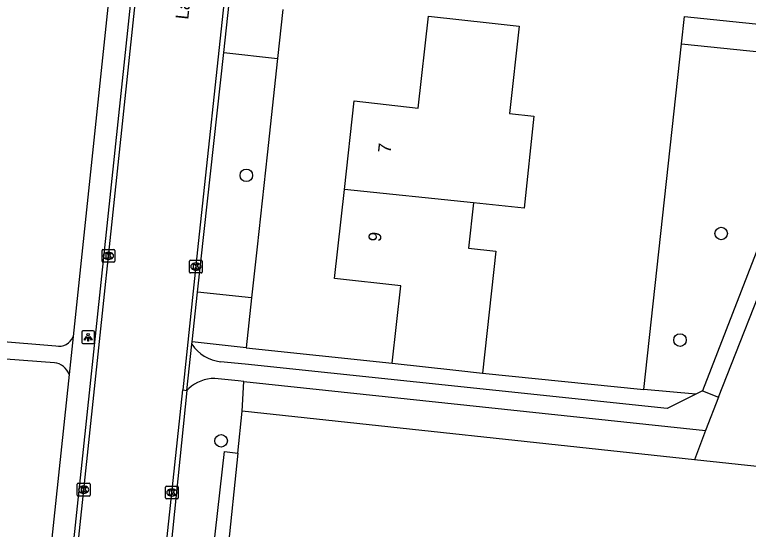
# Model space of a CAD drawing. Extents: x 162157 to 163165, y 378998 to 380775.
# Drawn here: x 162279.4 to 162336.8, y 380517.1 to 380557.3 of the extents above; entities that cross this region are included whole.
import ezdxf

# ---------------------------------------------------------------- set-up
doc = ezdxf.new("R2010")
doc.units = 0
for name, color, linetype in [('IMGEO_Boom', 7, 'Continuous'), ('IMGEO_Groenvoorziening', 7, 'Continuous'), ('IMGEO_Kolk', 7, 'Continuous'), ('IMGEO_Lichtpunt', 7, 'Continuous'), ('IMGEO_Openbare_ruimte_label', 7, 'Continuous'), ('IMGEO_Pand', 7, 'Continuous'), ('IMGEO_Pand_nummerreeks', 7, 'Continuous'), ('IMGEO_Rijbaan_lokaal_gesloten', 7, 'Continuous'), ('IMGEO_Rijbaan_lokaal_open', 7, 'Continuous'), ('IMGEO_Voetpad_halfverhard', 7, 'Continuous'), ('IMGEO_Voetpad_open', 7, 'Continuous')]:
    doc.layers.add(name, color=color, linetype=linetype)

msp = doc.modelspace()

# ---------------------------------------------------------------- linework, layer by layer
at = {"layer": 'IMGEO_Boom'}
for centre in [(162297.53, 380544.794), (162334.65, 380540.252), (162331.431, 380531.924), (162295.554, 380524.053)]:
    msp.add_circle(centre, 0.489, dxfattribs=at)
at = {"layer": 'IMGEO_Groenvoorziening'}
for points in [[(162331.554, 380555.055), (162331.789, 380557.201), (162360.519, 380554.228), (162361.274, 380554.214), (162362.768, 380554.423), (162364.185, 380554.938), (162365.465, 380555.737), (162366.035, 380556.232), (162366.969, 380557.333)], [(162328.597, 380528.068), (162331.554, 380555.055)], [(162331.554, 380555.055), (162343.253, 380553.86)], [(162299.968, 380553.918), (162299.151, 380546.402), (162298.369, 380539.218), (162297.934, 380535.219)], [(162351.197, 380550.17), (162347.945, 380520.935), (162332.573, 380522.579)], [(162297.511, 380531.329), (162308.934, 380530.109)], [(162315.978, 380529.334), (162328.597, 380528.068)], [(162297.191, 380526.364), (162297.341, 380528.688)], [(162332.674, 380527.708), (162328.597, 380528.068)], [(162296.858, 380523.1), (162297.191, 380526.364)], [(162332.573, 380522.579), (162297.191, 380526.364)], [(162333.411, 380524.874), (162332.573, 380522.579)], [(162294.943, 380515.381), (162295.812, 380523.22), (162296.858, 380523.1)], [(162296.858, 380523.1), (162296.058, 380515.267)]]:
    msp.add_lwpolyline(points, dxfattribs=at)
at = {"layer": 'IMGEO_Kolk'}
for p, q in [((162286.246, 380538.083), (162286.246, 380538.935)), ((162286.321, 380539.009), (162287.173, 380539.009)), ((162286.734, 380538.789), (162286.759, 380538.789)), ((162287.247, 380538.935), (162287.247, 380538.083)), ((162287.173, 380538.009), (162286.321, 380538.009)), ((162286.757, 380538.229), (162286.732, 380538.229)), ((162293.082, 380537.242), (162293.082, 380538.094)), ((162293.157, 380538.168), (162294.009, 380538.168)), ((162293.57, 380537.948), (162293.595, 380537.948)), ((162294.083, 380538.094), (162294.083, 380537.242)), ((162293.593, 380537.388), (162293.568, 380537.388)), ((162294.009, 380537.168), (162293.157, 380537.168)), ((162284.387, 380520.739), (162285.239, 380520.739)), ((162284.312, 380519.813), (162284.312, 380520.665)), ((162284.8, 380520.519), (162284.825, 380520.519)), ((162285.313, 380520.665), (162285.313, 380519.813)), ((162291.209, 380519.589), (162291.209, 380520.441)), ((162291.284, 380520.515), (162292.136, 380520.515)), ((162291.697, 380520.295), (162291.722, 380520.295)), ((162292.21, 380520.441), (162292.21, 380519.589)), ((162285.239, 380519.739), (162284.387, 380519.739)), ((162284.823, 380519.959), (162284.798, 380519.959)), ((162291.72, 380519.735), (162291.695, 380519.735)), ((162292.136, 380519.515), (162291.284, 380519.515))]:
    msp.add_line(p, q, dxfattribs=at)
for points in [[(162286.246, 380538.083), (162286.246, 380538.935)], [(162286.321, 380539.009), (162287.173, 380539.009)], [(162286.567, 380538.709), (162286.69, 380538.709), (162286.69, 380538.558), (162286.82, 380538.709), (162286.984, 380538.709), (162286.838, 380538.558), (162286.991, 380538.309), (162286.839, 380538.309), (162286.754, 380538.473), (162286.69, 380538.406), (162286.69, 380538.309), (162286.567, 380538.309), (162286.567, 380538.709)], [(162287.247, 380538.935), (162287.247, 380538.083)], [(162287.173, 380538.009), (162286.321, 380538.009)], [(162293.082, 380537.242), (162293.082, 380538.094)], [(162293.157, 380538.168), (162294.009, 380538.168)], [(162294.083, 380538.094), (162294.083, 380537.242)], [(162293.403, 380537.868), (162293.526, 380537.868), (162293.526, 380537.717), (162293.656, 380537.868), (162293.82, 380537.868), (162293.674, 380537.717), (162293.827, 380537.468), (162293.675, 380537.468), (162293.59, 380537.632), (162293.526, 380537.565), (162293.526, 380537.468), (162293.403, 380537.468), (162293.403, 380537.868)], [(162294.009, 380537.168), (162293.157, 380537.168)], [(162284.387, 380520.739), (162285.239, 380520.739)], [(162284.312, 380519.813), (162284.312, 380520.665)], [(162284.633, 380520.439), (162284.756, 380520.439), (162284.756, 380520.288), (162284.886, 380520.439), (162285.05, 380520.439), (162284.904, 380520.288), (162285.057, 380520.039), (162284.905, 380520.039), (162284.82, 380520.203), (162284.756, 380520.136), (162284.756, 380520.039), (162284.633, 380520.039), (162284.633, 380520.439)], [(162285.313, 380520.665), (162285.313, 380519.813)], [(162291.209, 380519.589), (162291.209, 380520.441)], [(162291.284, 380520.515), (162292.136, 380520.515)], [(162291.53, 380520.215), (162291.653, 380520.215), (162291.653, 380520.064), (162291.783, 380520.215), (162291.947, 380520.215), (162291.801, 380520.064), (162291.954, 380519.815), (162291.802, 380519.815), (162291.717, 380519.979), (162291.653, 380519.912), (162291.653, 380519.815), (162291.53, 380519.815), (162291.53, 380520.215)], [(162292.21, 380520.441), (162292.21, 380519.589)], [(162285.239, 380519.739), (162284.387, 380519.739)], [(162292.136, 380519.515), (162291.284, 380519.515)]]:
    msp.add_lwpolyline(points, dxfattribs=at)
for centre, start, end in [((162286.323, 380538.933), 91.55205, 178.44795), ((162286.323, 380538.933), 91.55205, 178.44795), ((162287.171, 380538.933), 1.55205, 88.44795), ((162287.171, 380538.933), 1.55205, 88.44795), ((162286.323, 380538.085), 181.55205, 268.44795), ((162286.323, 380538.085), 181.55205, 268.44795), ((162287.171, 380538.085), 271.55205, 358.44795), ((162287.171, 380538.085), 271.55205, 358.44795), ((162293.159, 380538.092), 91.55205, 178.44795), ((162293.159, 380538.092), 91.55205, 178.44795), ((162294.007, 380538.092), 1.55205, 88.44795), ((162294.007, 380538.092), 1.55205, 88.44795), ((162293.159, 380537.244), 181.55205, 268.44795), ((162293.159, 380537.244), 181.55205, 268.44795), ((162294.007, 380537.244), 271.55205, 358.44795), ((162294.007, 380537.244), 271.55205, 358.44795), ((162284.389, 380520.663), 91.55205, 178.44795), ((162284.389, 380520.663), 91.55205, 178.44795), ((162285.237, 380520.663), 1.55205, 88.44795), ((162285.237, 380520.663), 1.55205, 88.44795), ((162291.286, 380520.439), 91.55205, 178.44795), ((162291.286, 380520.439), 91.55205, 178.44795), ((162292.134, 380520.439), 1.55205, 88.44795), ((162292.134, 380520.439), 1.55205, 88.44795), ((162284.389, 380519.815), 181.55205, 268.44795), ((162284.389, 380519.815), 181.55205, 268.44795), ((162285.237, 380519.815), 271.55205, 358.44795), ((162285.237, 380519.815), 271.55205, 358.44795), ((162291.286, 380519.591), 181.55205, 268.44795), ((162291.286, 380519.591), 181.55205, 268.44795), ((162292.134, 380519.591), 271.55205, 358.44795), ((162292.134, 380519.591), 271.55205, 358.44795)]:
    msp.add_arc(centre, 0.0765, start, end, dxfattribs=at)
for centre, major_axis, ratio, start_param, end_param in [((162286.733, 380538.509), (-0.387, 0.002), 0.722429, 4.712389, 7.853982), ((162286.758, 380538.509), (-0.39, 0.002), 0.717154, 1.570796, 4.712389), ((162293.569, 380537.668), (-0.387, 0.002), 0.722429, 4.712389, 7.853982), ((162293.594, 380537.668), (-0.39, 0.002), 0.717154, 1.570796, 4.712389), ((162284.799, 380520.239), (-0.387, 0.002), 0.722429, 4.712389, 7.853982), ((162284.824, 380520.239), (-0.39, 0.002), 0.717154, 1.570796, 4.712389), ((162291.696, 380520.015), (-0.387, 0.002), 0.722429, 4.712389, 7.853982), ((162291.721, 380520.015), (-0.39, 0.002), 0.717154, 1.570796, 4.712389)]:
    msp.add_ellipse(centre, major_axis=major_axis, ratio=ratio, start_param=start_param, end_param=end_param, dxfattribs=at)
at = {"layer": 'IMGEO_Lichtpunt'}
for p, q in [((162284.657, 380532.548), (162284.657, 380531.741)), ((162284.657, 380532.548), (162284.657, 380531.741)), ((162285.559, 380532.643), (162284.751, 380532.643)), ((162285.559, 380532.643), (162284.751, 380532.643)), ((162285.653, 380531.741), (162285.653, 380532.548)), ((162285.653, 380531.741), (162285.653, 380532.548)), ((162284.751, 380531.647), (162285.559, 380531.647)), ((162284.751, 380531.647), (162285.559, 380531.647))]:
    msp.add_line(p, q, dxfattribs=at)
for points in [[(162285.031, 380532.212), (162285.07, 380532.184), (162284.882, 380531.922), (162284.844, 380531.949), (162285.031, 380532.212)], [(162285.133, 380532.164), (162285.18, 380532.164), (162285.18, 380531.842), (162285.133, 380531.842), (162285.133, 380532.164)], [(162285.243, 380532.184), (162285.281, 380532.211), (162285.468, 380531.949), (162285.429, 380531.921), (162285.243, 380532.184)]]:
    msp.add_lwpolyline(points, dxfattribs=at)
msp.add_circle((162285.156, 380532.346), 0.0994, dxfattribs=at)
for centre, start, end in [((162284.751, 380532.548), 90, 180), ((162284.751, 380532.548), 90, 180), ((162285.559, 380532.548), 0, 90), ((162285.559, 380532.548), 0, 90), ((162284.751, 380531.741), 180, 270), ((162284.751, 380531.741), 180, 270), ((162285.559, 380531.741), 270, 0), ((162285.559, 380531.741), 270, 360)]:
    msp.add_arc(centre, 0.0946, start, end, dxfattribs=at)
at = {"layer": 'IMGEO_Pand'}
for points in [[(162305.192, 380543.685), (162305.953, 380550.603), (162310.971, 380550.05), (162311.762, 380557.239), (162316.733, 380556.692), (162318.843, 380556.46), (162318.091, 380549.621), (162319.999, 380549.424), (162319.256, 380542.232), (162315.28, 380542.643)], [(162308.934, 380530.109), (162309.601, 380536.17), (162304.427, 380536.739), (162305.192, 380543.685)], [(162315.28, 380542.643), (162305.192, 380543.685)], [(162315.28, 380542.643), (162314.89, 380539.1), (162317.027, 380538.865), (162315.978, 380529.334)], [(162308.934, 380530.109), (162313.905, 380529.562), (162315.978, 380529.334)]]:
    msp.add_lwpolyline(points, dxfattribs=at)
at = {"layer": 'IMGEO_Rijbaan_lokaal_gesloten'}
for points in [[(162302.301, 380620.086), (162302.073, 380618.08), (162298.145, 380580.349), (162293.721, 380538.975), (162292.56, 380528.03)], [(162281.641, 380490.186), (162282.669, 380500), (162283.691, 380509.63), (162295.231, 380618.617)], [(162286.68, 380471.979), (162288.117, 380486.031), (162288.128, 380486.137), (162289.589, 380500), (162290.022, 380504.113), (162292.56, 380528.03)], [(162292.885, 380527.995), (162291.624, 380515.72)], [(162292.56, 380528.03), (162292.885, 380527.995)]]:
    msp.add_lwpolyline(points, dxfattribs=at)
at = {"layer": 'IMGEO_Rijbaan_lokaal_open'}
for points in [[(162294.853, 380618.658), (162282.29, 380500), (162281.985, 380496.996)], [(162295.764, 380554.384), (162296.186, 380558.246)], [(162293.722, 380535.67), (162295.764, 380554.384)], [(162293.298, 380531.779), (162293.722, 380535.67)], [(162292.885, 380527.995), (162293.278, 380531.599)], [(162293.278, 380531.599), (162293.298, 380531.779)]]:
    msp.add_lwpolyline(points, dxfattribs=at)
at = {"layer": 'IMGEO_Voetpad_halfverhard'}
for points in [[(162343.253, 380553.86), (162333.176, 380527.959)], [(162334.433, 380527.463), (162343.35, 380550.063), (162344.545, 380550.905)], [(162259.846, 380533.285), (162277.893, 380531.855), (162282.641, 380531.479)], [(162282.528, 380530.159), (162278.715, 380530.436)], [(162332.674, 380527.708), (162330.425, 380526.582), (162297.428, 380530.037), (162295.508, 380530.238)], [(162297.341, 380528.688), (162296.892, 380528.735), (162295.054, 380528.929)], [(162297.341, 380528.688), (162333.411, 380524.874)], [(162293.032, 380528.137), (162292.885, 380527.995)], [(162333.176, 380527.959), (162332.674, 380527.708)], [(162333.176, 380527.959), (162334.433, 380527.463)], [(162334.433, 380527.463), (162333.411, 380524.874)]]:
    msp.add_lwpolyline(points, dxfattribs=at)
for centre, radius, start, end in [((162282.896, 380532.609), 1.158, 257.28887, 339.11824), ((162295.831, 380533.274), 3.053, 213.27456, 263.93285), ((162282.363, 380528.79), 1.379, 19.09054, 83.12472), ((162295.083, 380525.879), 3.05, 90.53545, 132.24425)]:
    msp.add_arc(centre, radius, start, end, dxfattribs=at)
at = {"layer": 'IMGEO_Voetpad_open'}
for points in [[(162293.218, 380619.805), (162283.978, 380532.196)], [(162300.384, 380557.742), (162299.968, 380553.918)], [(162295.764, 380554.384), (162299.968, 380553.918)], [(162297.934, 380535.219), (162293.722, 380535.67)], [(162297.934, 380535.219), (162297.511, 380531.329)], [(162283.978, 380532.196), (162283.666, 380529.241)], [(162297.511, 380531.329), (162293.298, 380531.779)], [(162283.666, 380529.241), (162280.583, 380500), (162280.121, 380495.613)]]:
    msp.add_lwpolyline(points, dxfattribs=at)

# ---------------------------------------------------------------- texts
at = {"layer": 'IMGEO_Openbare_ruimte_label'}
msp.add_text('Landsteinerlaan', height=1, rotation=83.74207, dxfattribs=at).set_placement((162292.985, 380556.933))
at = {"layer": 'IMGEO_Pand_nummerreeks'}
for s, rotation, p in [('7', 83.72059, (162308.802, 380546.504)), ('9', 83.71878, (162308.038, 380539.572))]:
    msp.add_text(s, height=1, rotation=rotation, dxfattribs=at).set_placement(p)

doc.saveas('drawing.dxf')
